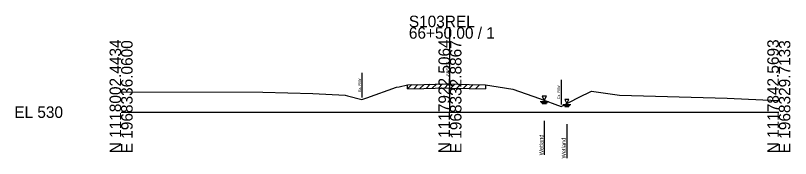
# Model space of a CAD drawing. Extents: x -26 to 163, y -10 to 24518.
# Drawn here: x -25.7 to 162.8, y 14988.7 to 15023.5 of the extents above; entities that cross this region are included whole.
import ezdxf

# ---------------------------------------------------------------- set-up
doc = ezdxf.new("R2010")
doc.units = 0
for name, color, linetype in [('RD_GPK_XS_Cell', 7, 'Continuous'), ('RD_XS_ExGround', 7, 'Continuous'), ('RD_XS_ExPaveRet', 7, 'Continuous'), ('RD_XS_ExRW', 7, 'Continuous'), ('RD_XS_EXWetland', 7, 'Continuous'), ('RD_XS_TX_Elev_EX', 7, 'Continuous')]:
    doc.layers.add(name, color=color, linetype=linetype)

msp = doc.modelspace()

# ---------------------------------------------------------------- linework, layer by layer
at = {"layer": 'RD_GPK_XS_Cell'}
for p, q in [((80, 15000), (80, 15020.66)), ((0, 15000), (80, 15000)), ((80, 15000), (160, 15000))]:
    msp.add_line(p, q, dxfattribs=at)
at = {"layer": 'RD_XS_ExGround'}
msp.add_lwpolyline([(0, 15004.96), (34.48, 15004.85), (46.63, 15004.53), (54.47, 15004.14), (55.1, 15003.98), (58.58, 15003.05), (59.81, 15003.49), (67.01, 15006.08), (67.65, 15006.19), (69.68, 15006.66), (73.61, 15006.75), (79.19, 15006.89), (80, 15006.86), (84.7, 15006.74), (88.61, 15006.64), (91.7, 15006.17), (95.29, 15005.6), (101.78, 15003.3), (107.03, 15001.36), (111.24, 15003.56), (114.39, 15005.1), (121.27, 15004.16), (147.45, 15003.4), (156.14, 15002.96), (160, 15002.82)], dxfattribs=at)
at = {"layer": 'RD_XS_ExPaveRet'}
for p, q in [((69.68, 15005.66), (70.7, 15006.69)), ((69.68, 15005.66), (69.68, 15006.66)), ((69.68, 15005.66), (73.61, 15005.75)), ((71.18, 15005.7), (72.2, 15006.72)), ((72.68, 15005.73), (73.7, 15006.75)), ((73.61, 15005.75), (79.19, 15005.89)), ((74.18, 15005.77), (75.21, 15006.79)), ((75.68, 15005.8), (76.71, 15006.83)), ((77.18, 15005.84), (78.21, 15006.86)), ((78.68, 15005.87), (79.68, 15006.87)), ((79.19, 15005.89), (80, 15005.86)), ((80, 15005.86), (84.7, 15005.74)), ((80.18, 15005.86), (81.16, 15006.83)), ((81.68, 15005.82), (82.66, 15006.79)), ((83.18, 15005.78), (84.16, 15006.75)), ((84.68, 15005.74), (85.66, 15006.72)), ((84.7, 15005.74), (88.61, 15005.64)), ((86.18, 15005.7), (87.16, 15006.68)), ((88.61, 15006.64), (88.61, 15005.64))]:
    msp.add_line(p, q, dxfattribs=at)
at = {"layer": 'RD_XS_ExRW'}
for p, q in [((58.58, 15009.55), (58.58, 15003.55)), ((107.03, 15007.86), (107.03, 15001.86))]:
    msp.add_line(p, q, dxfattribs=at)
at = {"layer": 'RD_XS_EXWetland'}
for p, q in [((102.45, 15003.87), (102.95, 15002.87)), ((103.45, 15003.87), (102.45, 15003.87)), ((102.45, 15003.87), (102.95, 15002.87)), ((103.45, 15003.87), (102.45, 15003.87)), ((102.95, 15002.87), (103.45, 15003.87)), ((102.95, 15002.87), (103.45, 15003.87)), ((101.95, 15002.62), (103.95, 15002.62)), ((101.95, 15002.62), (103.95, 15002.62)), ((102.2, 15002.37), (103.7, 15002.37)), ((102.2, 15002.37), (103.7, 15002.37)), ((102.45, 15002.12), (103.45, 15002.12)), ((102.45, 15002.12), (103.45, 15002.12)), ((107.42, 15001.84), (109.42, 15001.84)), ((107.42, 15001.84), (109.42, 15001.84)), ((107.67, 15001.59), (109.17, 15001.59)), ((107.67, 15001.59), (109.17, 15001.59)), ((107.92, 15003.09), (108.42, 15002.09)), ((108.92, 15003.09), (107.92, 15003.09)), ((107.92, 15003.09), (108.42, 15002.09)), ((108.92, 15003.09), (107.92, 15003.09)), ((108.42, 15002.09), (108.92, 15003.09)), ((108.42, 15002.09), (108.92, 15003.09)), ((107.92, 15001.34), (108.92, 15001.34)), ((107.92, 15001.34), (108.92, 15001.34)), ((102.95, 14997.87), (102.95, 14989.62)), ((102.95, 14997.87), (102.95, 14989.62)), ((108.42, 14997.09), (108.42, 14988.84)), ((108.42, 14997.09), (108.42, 14988.84))]:
    msp.add_line(p, q, dxfattribs=at)

# ---------------------------------------------------------------- texts
at = {"layer": 'RD_GPK_XS_Cell'}
for s, p in [('S103REL', (70, 15020.66)), ('66+50.00 / 1', (70, 15017.86)), ('EL 530', (-26, 14998.6))]:
    msp.add_text(s, height=2.8, dxfattribs=at).set_placement(p)
for s, p in [('N 1118002.4434', (0, 14990)), ('E 1968336.0600', (2.8, 14990)), ('N 1117922.5064', (80, 14990)), ('E 1968332.8867', (82.8, 14990)), ('N 1117842.5693', (160, 14990)), ('E 1968329.7133', (162.8, 14990))]:
    msp.add_text(s, height=2.8, rotation=90, dxfattribs=at).set_placement(p)
at = {"layer": 'RD_XS_ExRW'}
for p in [(58.33, 15004.89), (106.78, 15003.21)]:
    msp.add_text('Ex. R/W ', height=0.65, rotation=90, dxfattribs=at).set_placement(p)
at = {"layer": 'RD_XS_EXWetland'}
for p in [(102.7, 14989.51), (102.7, 14989.51), (108.17, 14988.73), (108.17, 14988.73)]:
    msp.add_text('Wetland ', height=1, rotation=90, dxfattribs=at).set_placement(p)
at = {"layer": 'RD_XS_TX_Elev_EX'}
msp.add_text('536.86', height=0.8, rotation=90, dxfattribs=at).set_placement((79.9, 15008.86))

doc.saveas('drawing.dxf')
